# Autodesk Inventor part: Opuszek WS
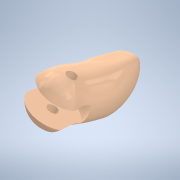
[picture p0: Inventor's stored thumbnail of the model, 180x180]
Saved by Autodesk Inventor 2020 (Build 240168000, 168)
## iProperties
Created: 2019-10
Part Number: Opuszek WS
Material: Laiton, jaune doux, soudé
Document SubType Name: Modeling
Designer: yello
Density: 8.5 g/cm^3
Appearance: Soudure - Laiton
Author: yello
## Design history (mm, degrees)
feature "Opuszek WS"
sketch "Sketch1"
  geometry: C1 r 2 at (0, 0); 1 further point
  constraints: 1 centre point
  dimensions: "d0" = 4 diameter of C1
extrude "Extrusion1" cut sketch "Sketch1" stored distance "d1" = 100; taper "d2" = 0 deg
body "Solid1"
